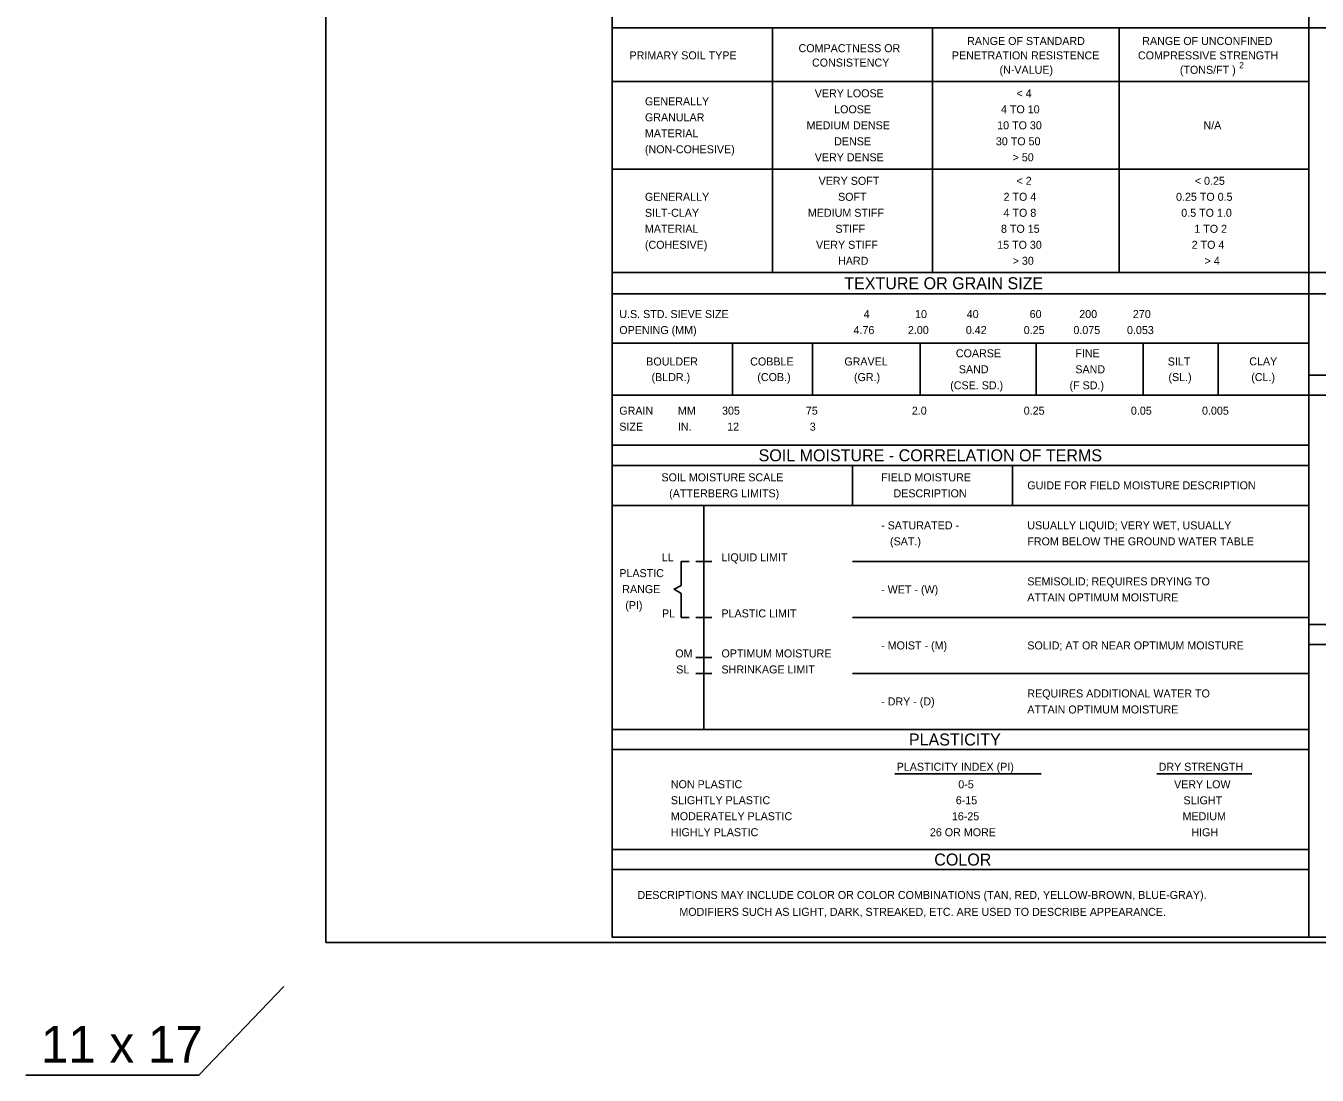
# Model space of a CAD drawing. Extents: x 265553 to 275568, y 168312 to 173522.
# Drawn here: x 266603 to 267302, y 170175 to 170744 of the extents above; entities that cross this region are included whole.
import ezdxf

# ---------------------------------------------------------------- set-up
doc = ezdxf.new("R2010")
doc.units = 0
for name, color, linetype in [('Geotech Sheets and Borders Cell', 7, 'Continuous'), ('Scratch_Level_0', 7, 'Continuous'), ('Sheet Plot Border Inside CELL', 7, 'Continuous')]:
    doc.layers.add(name, color=color, linetype=linetype)

msp = doc.modelspace()

# ---------------------------------------------------------------- linework, layer by layer
at = {"layer": 'Geotech Sheets and Borders Cell'}
for p, q in [((267297.82, 171052.08), (267297.82, 170249.94)), ((267670.42, 170742.87), (266920.42, 170742.87)), ((267007.18, 170742.87), (267007.18, 170610.2)), ((267093.94, 170742.87), (267093.94, 170610.2)), ((267195.08, 170742.87), (267195.08, 170610.2)), ((266920.42, 170713.71), (267297.82, 170713.71)), ((266920.42, 170666.29), (267297.82, 170666.29)), ((266920.42, 170610.2), (267670.42, 170610.2)), ((266920.42, 170598.59), (267670.42, 170598.59)), ((266920.42, 170571.86), (267297.82, 170571.86)), ((266985.49, 170571.86), (266985.49, 170543.66)), ((267028.87, 170571.86), (267028.87, 170543.66)), ((267087.34, 170571.86), (267087.34, 170543.66)), ((267150.11, 170571.86), (267150.11, 170543.66)), ((267208.2, 170571.86), (267208.2, 170543.66)), ((267248.85, 170571.86), (267248.85, 170543.66)), ((267297.82, 170554.51), (267670.42, 170554.51)), ((266920.42, 170543.66), (267297.82, 170543.66)), ((267297.82, 170543.66), (267670.42, 170543.66)), ((266920.42, 170516.56), (267297.82, 170516.56)), ((266920.42, 170505.71), (267297.82, 170505.71)), ((267050.56, 170505.71), (267050.56, 170484.02)), ((267137.32, 170505.71), (267137.32, 170484.02)), ((266920.42, 170484.02), (267297.82, 170484.02)), ((266969.99, 170484.02), (266969.99, 170362.56)), ((266974.33, 170453.66), (266965.66, 170453.66)), ((266969.99, 170453.66), (266974.33, 170453.66)), ((267050.56, 170453.66), (267297.82, 170453.66)), ((266974.33, 170423.29), (266965.66, 170423.29)), ((267050.56, 170423.29), (267297.82, 170423.29)), ((267297.82, 170419.46), (267670.42, 170419.46)), ((267297.82, 170408.61), (267670.42, 170408.61)), ((266974.33, 170401.6), (266965.66, 170401.6)), ((266974.33, 170392.92), (266965.66, 170392.92)), ((267050.56, 170392.92), (267297.82, 170392.92)), ((266920.42, 170362.56), (267297.82, 170362.56)), ((266920.42, 170351.71), (267297.82, 170351.71)), ((267073.61, 170338.6), (267152.89, 170338.6)), ((267215.57, 170338.6), (267267.01, 170338.6)), ((266920.42, 170297.49), (267297.82, 170297.49)), ((266920.42, 170286.64), (267297.82, 170286.64))]:
    msp.add_line(p, q, dxfattribs=at)
msp.add_lwpolyline([(266920.42, 171299.94), (268420.42, 171299.94), (268420.42, 170249.94), (266920.42, 170249.94)], close=True, dxfattribs=at)
for points in [[(266962.14, 170453.66), (266957.8, 170453.66), (266957.8, 170440.65)], [(266957.8, 170440.65), (266953.9, 170438.61), (266957.8, 170436.18)], [(266962.14, 170423.29), (266957.8, 170423.29), (266957.8, 170436.18)]]:
    msp.add_lwpolyline(points, dxfattribs=at)
at = {"layer": 'Scratch_Level_0'}
msp.add_line((266765.25, 170247.11), (266765.25, 170247.11), dxfattribs=at)
msp.add_lwpolyline([(266602.6, 170175.2), (266696.43, 170175.2), (266742.35, 170223.18)], dxfattribs=at)
at = {"layer": 'Sheet Plot Border Inside CELL'}
msp.add_lwpolyline([(266765.25, 170247.11), (268432.92, 170247.11), (268432.92, 171302.77), (266765.25, 171302.77)], close=True, dxfattribs=at)

# ---------------------------------------------------------------- texts
at = {"layer": 'Geotech Sheets and Borders Cell'}
for s, height, p in [('RANGE OF STANDARD', 4.3381, (267112.71, 170733.53)), ('RANGE OF UNCONFINED', 4.3381, (267207.63, 170733.53)), ('PRIMARY SOIL TYPE', 4.3381, (266929.76, 170725.72)), ('COMPACTNESS OR', 4.3381, (267021.37, 170729.62)), ('PENETRATION RESISTENCE', 4.3381, (267104.47, 170725.72)), ('COMPRESSIVE STRENGTH', 4.3381, (267205.31, 170725.72)), ('CONSISTENCY', 4.3381, (267028.65, 170721.82)), ('2', 3.47, (267260.14, 170720.82)), ('(N-VALUE)', 4.338, (267130.28, 170717.91)), ('(TONS/FT )', 4.338, (267228.01, 170717.91)), ('VERY LOOSE', 4.338, (267030.15, 170705.16)), ('< 4', 4.338, (267139.47, 170705.16)), ('GENERALLY', 4.338, (266938.11, 170700.83)), ('GRANULAR', 4.338, (266938.11, 170692.16)), ('LOOSE', 4.338, (267040.67, 170696.5)), ('4 TO 10', 4.338, (267131.07, 170696.5)), ('MEDIUM DENSE', 4.3381, (267025.74, 170687.83)), ('10 TO 30', 4.338, (267129.02, 170687.83)), ('N/A', 4.338, (267240.8, 170687.83)), ('MATERIAL', 4.338, (266938.11, 170683.49)), ('DENSE', 4.338, (267040.67, 170679.16)), ('30 TO 50', 4.338, (267128.3, 170679.16)), ('(NON-COHESIVE)', 4.3381, (266938.11, 170674.83)), ('VERY DENSE', 4.338, (267030.15, 170670.49)), ('> 50', 4.338, (267137.36, 170670.49)), ('VERY SOFT', 4.338, (267032.25, 170657.74)), ('< 2', 4.338, (267139.47, 170657.74)), ('< 0.25', 4.338, (267236.12, 170657.74)), ('GENERALLY', 4.338, (266938.11, 170649.08)), ('SOFT', 4.338, (267042.77, 170649.08)), ('2 TO 4', 4.338, (267132.47, 170649.08)), ('0.25 TO 0.5', 4.3381, (267225.94, 170649.08)), ('SILT-CLAY', 4.338, (266938.11, 170640.41)), ('MEDIUM STIFF', 4.3381, (267026.43, 170640.41)), ('4 TO 8', 4.338, (267132.47, 170640.41)), ('0.5 TO 1.0', 4.338, (267228.78, 170640.41)), ('MATERIAL', 4.338, (266938.11, 170631.74)), ('STIFF', 4.338, (267041.35, 170631.74)), ('8 TO 15', 4.338, (267131.07, 170631.74)), ('1 TO 2', 4.338, (267235.85, 170631.74)), ('(COHESIVE)', 4.338, (266938.11, 170623.07)), ('VERY STIFF', 4.338, (267030.83, 170623.07)), ('15 TO 30', 4.338, (267129.02, 170623.07)), ('2 TO 4', 4.338, (267234.41, 170623.07)), ('HARD', 4.338, (267042.79, 170614.4)), ('> 30', 4.338, (267137.42, 170614.4)), ('> 4', 4.338, (267241.41, 170614.4)), ('TEXTURE OR GRAIN SIZE', 6.507, (267046.13, 170601.14)), ('U.S. STD. SIEVE SIZE', 4.3381, (266924.23, 170585.53)), ('10', 4.338, (267084.52, 170585.53)), (' 40 ', 4.338, (267110.91, 170585.53)), ('60', 4.338, (267146.61, 170585.53)), ('200', 4.338, (267173.5, 170585.53)), ('270', 4.338, (267202.55, 170585.53)), ('4', 4.34, (267056.69, 170585.53)), ('OPENING (MM)', 4.3381, (266924.23, 170576.85)), ('4.76   ', 4.338, (267051.16, 170576.85)), ('2.00', 4.338, (267080.63, 170576.85)), ('0.42', 4.338, (267112.01, 170576.85)), ('0.25', 4.338, (267143.4, 170576.85)), ('0.075', 4.338, (267170.33, 170576.85)), ('0.053', 4.338, (267199.37, 170576.85)), ('BOULDER', 4.338, (266938.83, 170559.82)), ('COBBLE', 4.338, (266995.17, 170559.82)), ('GRAVEL', 4.338, (267046.17, 170559.82)), ('COARSE', 4.338, (267106.62, 170564.27)), ('FINE', 4.338, (267171.38, 170564.27)), ('SILT', 4.338, (267221.45, 170559.82)), ('CLAY', 4.338, (267265.63, 170559.89)), ('(BLDR.)', 4.338, (266941.69, 170551.36)), ('(COB.)', 4.338, (266999.03, 170551.36)), ('(GR.)', 4.338, (267051.41, 170551.36)), (' SAND', 4.338, (267106.62, 170555.59)), ('SAND', 4.338, (267171.38, 170555.59)), ('(SL.)', 4.338, (267221.83, 170551.36)), ('(CL.)', 4.338, (267266.71, 170551.36)), ('(CSE. SD.)', 4.338, (267103.56, 170546.91)), ('(F SD.)', 4.338, (267168.22, 170546.91)), ('GRAIN', 4.338, (266924.23, 170533.17)), ('MM', 4.338, (266955.98, 170533.17)), ('305', 4.338, (266979.9, 170533.17)), ('75', 4.338, (267025.33, 170533.17)), ('2.0', 4.338, (267082.75, 170533.17)), ('0.25', 4.338, (267143.4, 170533.17)), ('0.05', 4.338, (267201.49, 170533.17)), ('0.005', 4.338, (267240.02, 170533.17)), ('SIZE', 4.338, (266924.23, 170524.49)), ('IN.', 4.338, (266955.98, 170524.5)), ('12', 4.338, (266982.67, 170524.51)), ('3', 4.34, (267027.45, 170524.51)), ('SOIL MOISTURE - CORRELATION OF TERMS', 6.507, (266999.71, 170507.88)), ('SOIL MOISTURE SCALE', 4.3381, (266947.08, 170497.03)), ('FIELD MOISTURE', 4.3381, (267066.12, 170497.03)), ('(ATTERBERG LIMITS)', 4.3381, (266951.26, 170488.36)), ('DESCRIPTION', 4.3381, (267072.81, 170488.36)), ('GUIDE FOR FIELD MOISTURE DESCRIPTION', 4.3381, (267145.34, 170492.7)), ('- SATURATED -', 4.3381, (267066.12, 170471.01)), ('USUALLY LIQUID; VERY WET, USUALLY', 4.3381, (267145.34, 170471.01)), ('   (SAT.)', 4.338, (267066.12, 170462.34)), ('FROM BELOW THE GROUND WATER TABLE', 4.3381, (267145.34, 170462.34)), ('LL', 4.338, (266947.21, 170453.66)), ('LIQUID LIMIT', 4.3381, (266979.6, 170453.66)), ('PLASTIC', 4.338, (266924.23, 170445.12)), ('SEMISOLID; REQUIRES DRYING TO', 4.3381, (267145.34, 170440.64)), (' RANGE', 4.338, (266924.23, 170436.44)), ('- WET - (W)', 4.3381, (267066.12, 170436.31)), ('ATTAIN OPTIMUM MOISTURE', 4.3381, (267145.34, 170431.97)), ('  (PI)', 4.338, (266924.23, 170427.77)), ('PL', 4.338, (266947.35, 170423.29)), ('PLASTIC LIMIT', 4.3381, (266979.6, 170423.29)), ('- MOIST - (M)', 4.3381, (267066.12, 170405.94)), ('SOLID; AT OR NEAR OPTIMUM MOISTURE', 4.3381, (267145.34, 170405.94)), ('OM', 4.338, (266954.56, 170401.6)), ('OPTIMUM MOISTURE', 4.3381, (266979.6, 170401.6)), ('SL', 4.338, (266955.07, 170392.92)), ('SHRINKAGE LIMIT', 4.3381, (266979.6, 170392.92)), ('- DRY - (D)', 4.3381, (267066.12, 170375.57)), ('REQUIRES ADDITIONAL WATER TO', 4.3381, (267145.34, 170379.91)), ('ATTAIN OPTIMUM MOISTURE', 4.3381, (267145.34, 170371.23)), ('PLASTICITY', 6.507, (267081.17, 170353.88)), ('PLASTICITY INDEX (PI)', 4.3381, (267074.55, 170340.18)), ('DRY STRENGTH', 4.3381, (267216.51, 170340.18)), ('NON PLASTIC', 4.3381, (266952.17, 170330.71)), ('0-5', 4.338, (267107.94, 170330.68)), ('VERY LOW', 4.338, (267224.86, 170330.68)), ('SLIGHTLY PLASTIC', 4.3381, (266952.17, 170322.04)), ('6-15', 4.338, (267106.58, 170322.01)), ('SLIGHT', 4.338, (267229.98, 170322.01)), ('MODERATELY PLASTIC', 4.3381, (266952.17, 170313.37)), ('16-25', 4.338, (267104.46, 170313.35)), ('MEDIUM', 4.338, (267229.47, 170313.35)), ('HIGHLY PLASTIC', 4.3381, (266952.17, 170304.71)), ('26 OR MORE', 4.338, (267092.57, 170304.68)), ('HIGH', 4.338, (267234.23, 170304.68)), ('COLOR', 6.507, (267094.91, 170288.81)), ('DESCRIPTIONS MAY INCLUDE COLOR OR COLOR COMBINATIONS (TAN, RED, YELLOW-BROWN, BLUE-GRAY).', 4.3381, (266934.03, 170270.69)), ('MODIFIERS SUCH AS LIGHT, DARK, STREAKED, ETC. ARE USED TO DESCRIBE APPEARANCE.', 4.3381, (266956.78, 170261.55))]:
    msp.add_text(s, height=height, dxfattribs=at).set_placement(p)
at = {"layer": 'Scratch_Level_0'}
msp.add_text('11 x 17', height=20, dxfattribs=at).set_placement((266610.78, 170181.9))

doc.saveas('drawing.dxf')
